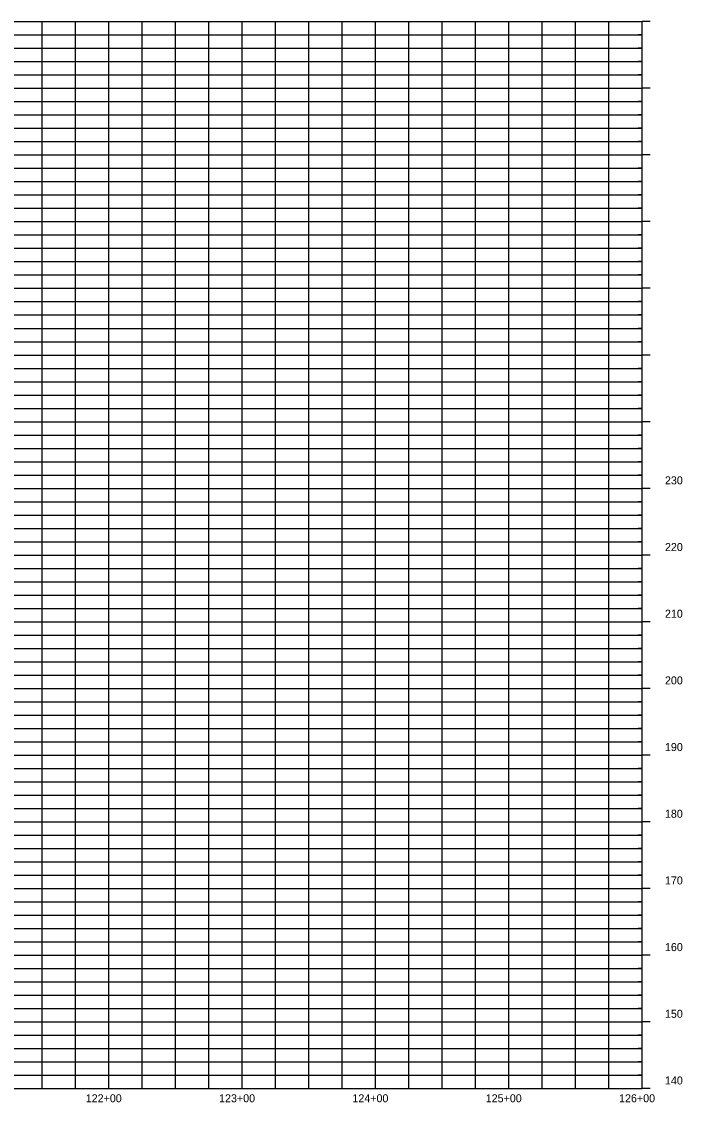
# Model space of a CAD drawing. Extents: x 1384498 to 1391279, y 1965973 to 1976560.
# Drawn here: x 1390583 to 1391079, y 1975299 to 1976110 of the extents above; entities that cross this region are included whole.
import ezdxf

# ---------------------------------------------------------------- set-up
doc = ezdxf.new("R2010")
doc.units = 0
for name, color, linetype in [('Default', 7, 'Continuous'), ('R_Axis_Annotation', 7, 'Continuous'), ('R_Grid', 7, 'Continuous'), ('R_Grid Annot', 7, 'Continuous'), ('R_Grid_Minor', 7, 'Continuous')]:
    doc.layers.add(name, color=color, linetype=linetype)

msp = doc.modelspace()

# ---------------------------------------------------------------- linework, layer by layer
at = {"layer": 'Default'}
msp.add_line((1388248.79, 1975309.84), (1390648.79, 1975309.84), dxfattribs=at)
at = {"layer": 'R_Grid'}
for p, q in [((1388248.79, 1976109.84), (1391048.79, 1976109.84)), ((1388248.79, 1976109.84), (1391048.79, 1976109.84)), ((1390648.79, 1975309.84), (1390648.79, 1976109.84)), ((1390748.79, 1975309.84), (1390748.79, 1976109.84)), ((1390848.79, 1975309.84), (1390848.79, 1976109.84)), ((1390948.79, 1975309.84), (1390948.79, 1976109.84)), ((1391048.79, 1975309.84), (1391048.79, 1976109.84)), ((1388248.79, 1976059.84), (1391048.79, 1976059.84)), ((1388248.79, 1976009.84), (1391048.79, 1976009.84)), ((1388248.79, 1975959.84), (1391048.79, 1975959.84)), ((1388248.79, 1975909.84), (1391048.79, 1975909.84)), ((1388248.79, 1975859.84), (1391048.79, 1975859.84)), ((1388248.79, 1975809.84), (1391048.79, 1975809.84)), ((1388248.79, 1975759.84), (1391048.79, 1975759.84)), ((1388248.79, 1975709.84), (1391048.79, 1975709.84)), ((1388248.79, 1975659.84), (1391048.79, 1975659.84)), ((1388248.79, 1975609.84), (1391048.79, 1975609.84)), ((1388248.79, 1975559.84), (1391048.79, 1975559.84)), ((1388248.79, 1975509.84), (1391048.79, 1975509.84)), ((1388248.79, 1975459.84), (1391048.79, 1975459.84)), ((1388248.79, 1975409.84), (1391048.79, 1975409.84)), ((1388248.79, 1975359.84), (1391048.79, 1975359.84)), ((1388248.79, 1975309.84), (1391048.79, 1975309.84))]:
    msp.add_line(p, q, dxfattribs=at)
at = {"layer": 'R_Grid Annot'}
for p, q in [((1391054.79, 1976109.84), (1391048.79, 1976109.84)), ((1391054.79, 1976109.84), (1391048.79, 1976109.84)), ((1391048.79, 1976099.84), (1391045.79, 1976099.84)), ((1391048.79, 1976089.84), (1391045.79, 1976089.84)), ((1391048.79, 1976079.84), (1391045.79, 1976079.84)), ((1391048.79, 1976069.84), (1391045.79, 1976069.84)), ((1391054.79, 1976059.84), (1391048.79, 1976059.84)), ((1391048.79, 1976049.84), (1391045.79, 1976049.84)), ((1391048.79, 1976039.84), (1391045.79, 1976039.84)), ((1391048.79, 1976029.84), (1391045.79, 1976029.84)), ((1391048.79, 1976019.84), (1391045.79, 1976019.84)), ((1391054.79, 1976009.84), (1391048.79, 1976009.84)), ((1391048.79, 1975999.84), (1391045.79, 1975999.84)), ((1391048.79, 1975989.84), (1391045.79, 1975989.84)), ((1391048.79, 1975979.84), (1391045.79, 1975979.84)), ((1391048.79, 1975969.84), (1391045.79, 1975969.84)), ((1391054.79, 1975959.84), (1391048.79, 1975959.84)), ((1391048.79, 1975949.84), (1391045.79, 1975949.84)), ((1391048.79, 1975939.84), (1391045.79, 1975939.84)), ((1391048.79, 1975929.84), (1391045.79, 1975929.84)), ((1391048.79, 1975919.84), (1391045.79, 1975919.84)), ((1391054.79, 1975909.84), (1391048.79, 1975909.84)), ((1391048.79, 1975899.84), (1391045.79, 1975899.84)), ((1391048.79, 1975889.84), (1391045.79, 1975889.84)), ((1391048.79, 1975879.84), (1391045.79, 1975879.84)), ((1391048.79, 1975869.84), (1391045.79, 1975869.84)), ((1391054.79, 1975859.84), (1391048.79, 1975859.84)), ((1391048.79, 1975849.84), (1391045.79, 1975849.84)), ((1391048.79, 1975839.84), (1391045.79, 1975839.84)), ((1391048.79, 1975829.84), (1391045.79, 1975829.84)), ((1391048.79, 1975819.84), (1391045.79, 1975819.84)), ((1391054.79, 1975809.84), (1391048.79, 1975809.84)), ((1391048.79, 1975799.84), (1391045.79, 1975799.84)), ((1391048.79, 1975789.84), (1391045.79, 1975789.84)), ((1391048.79, 1975779.84), (1391045.79, 1975779.84)), ((1391048.79, 1975769.84), (1391045.79, 1975769.84)), ((1391054.79, 1975759.84), (1391048.79, 1975759.84)), ((1391048.79, 1975749.84), (1391045.79, 1975749.84)), ((1391048.79, 1975739.84), (1391045.79, 1975739.84)), ((1391048.79, 1975729.84), (1391045.79, 1975729.84)), ((1391048.79, 1975719.84), (1391045.79, 1975719.84)), ((1391054.79, 1975709.84), (1391048.79, 1975709.84)), ((1391048.79, 1975699.84), (1391045.79, 1975699.84)), ((1391048.79, 1975689.84), (1391045.79, 1975689.84)), ((1391048.79, 1975679.84), (1391045.79, 1975679.84)), ((1391048.79, 1975669.84), (1391045.79, 1975669.84)), ((1391054.79, 1975659.84), (1391048.79, 1975659.84)), ((1391048.79, 1975649.84), (1391045.79, 1975649.84)), ((1391048.79, 1975639.84), (1391045.79, 1975639.84)), ((1391048.79, 1975629.84), (1391045.79, 1975629.84)), ((1391048.79, 1975619.84), (1391045.79, 1975619.84)), ((1391054.79, 1975609.84), (1391048.79, 1975609.84)), ((1391048.79, 1975599.84), (1391045.79, 1975599.84)), ((1391048.79, 1975589.84), (1391045.79, 1975589.84)), ((1391048.79, 1975579.84), (1391045.79, 1975579.84)), ((1391048.79, 1975569.84), (1391045.79, 1975569.84)), ((1391054.79, 1975559.84), (1391048.79, 1975559.84)), ((1391048.79, 1975549.84), (1391045.79, 1975549.84)), ((1391048.79, 1975539.84), (1391045.79, 1975539.84)), ((1391048.79, 1975529.84), (1391045.79, 1975529.84)), ((1391048.79, 1975519.84), (1391045.79, 1975519.84)), ((1391054.79, 1975509.84), (1391048.79, 1975509.84)), ((1391048.79, 1975499.84), (1391045.79, 1975499.84)), ((1391048.79, 1975489.84), (1391045.79, 1975489.84)), ((1391048.79, 1975479.84), (1391045.79, 1975479.84)), ((1391048.79, 1975469.84), (1391045.79, 1975469.84)), ((1391054.79, 1975459.84), (1391048.79, 1975459.84)), ((1391048.79, 1975449.84), (1391045.79, 1975449.84)), ((1391048.79, 1975439.84), (1391045.79, 1975439.84)), ((1391048.79, 1975429.84), (1391045.79, 1975429.84)), ((1391048.79, 1975419.84), (1391045.79, 1975419.84)), ((1391054.79, 1975409.84), (1391048.79, 1975409.84)), ((1391048.79, 1975399.84), (1391045.79, 1975399.84)), ((1391048.79, 1975389.84), (1391045.79, 1975389.84)), ((1391048.79, 1975379.84), (1391045.79, 1975379.84)), ((1391048.79, 1975369.84), (1391045.79, 1975369.84)), ((1391054.79, 1975359.84), (1391048.79, 1975359.84)), ((1391048.79, 1975349.84), (1391045.79, 1975349.84)), ((1391048.79, 1975339.84), (1391045.79, 1975339.84)), ((1391048.79, 1975329.84), (1391045.79, 1975329.84)), ((1391048.79, 1975319.84), (1391045.79, 1975319.84)), ((1391054.79, 1975309.84), (1391048.79, 1975309.84))]:
    msp.add_line(p, q, dxfattribs=at)
at = {"layer": 'R_Grid_Minor'}
for p, q in [((1390598.79, 1975309.84), (1390598.79, 1976109.84)), ((1390623.79, 1975309.84), (1390623.79, 1976109.84)), ((1390673.79, 1975309.84), (1390673.79, 1976109.84)), ((1390698.79, 1975309.84), (1390698.79, 1976109.84)), ((1390723.79, 1975309.84), (1390723.79, 1976109.84)), ((1390773.79, 1975309.84), (1390773.79, 1976109.84)), ((1390798.79, 1975309.84), (1390798.79, 1976109.84)), ((1390823.79, 1975309.84), (1390823.79, 1976109.84)), ((1390873.79, 1975309.84), (1390873.79, 1976109.84)), ((1390898.79, 1975309.84), (1390898.79, 1976109.84)), ((1390923.79, 1975309.84), (1390923.79, 1976109.84)), ((1390973.79, 1975309.84), (1390973.79, 1976109.84)), ((1390998.79, 1975309.84), (1390998.79, 1976109.84)), ((1391023.79, 1975309.84), (1391023.79, 1976109.84)), ((1388248.79, 1976099.84), (1391048.79, 1976099.84)), ((1388248.79, 1976089.84), (1391048.79, 1976089.84)), ((1388248.79, 1976079.84), (1391048.79, 1976079.84)), ((1388248.79, 1976069.84), (1391048.79, 1976069.84)), ((1388248.79, 1976049.84), (1391048.79, 1976049.84)), ((1388248.79, 1976039.84), (1391048.79, 1976039.84)), ((1388248.79, 1976029.84), (1391048.79, 1976029.84)), ((1388248.79, 1976019.84), (1391048.79, 1976019.84)), ((1388248.79, 1975999.84), (1391048.79, 1975999.84)), ((1388248.79, 1975989.84), (1391048.79, 1975989.84)), ((1388248.79, 1975979.84), (1391048.79, 1975979.84)), ((1388248.79, 1975969.84), (1391048.79, 1975969.84)), ((1388248.79, 1975949.84), (1391048.79, 1975949.84)), ((1388248.79, 1975939.84), (1391048.79, 1975939.84)), ((1388248.79, 1975929.84), (1391048.79, 1975929.84)), ((1388248.79, 1975919.84), (1391048.79, 1975919.84)), ((1388248.79, 1975899.84), (1391048.79, 1975899.84)), ((1388248.79, 1975889.84), (1391048.79, 1975889.84)), ((1388248.79, 1975879.84), (1391048.79, 1975879.84)), ((1388248.79, 1975869.84), (1391048.79, 1975869.84)), ((1388248.79, 1975849.84), (1391048.79, 1975849.84)), ((1388248.79, 1975839.84), (1391048.79, 1975839.84)), ((1388248.79, 1975829.84), (1391048.79, 1975829.84)), ((1388248.79, 1975819.84), (1391048.79, 1975819.84)), ((1388248.79, 1975799.84), (1391048.79, 1975799.84)), ((1388248.79, 1975789.84), (1391048.79, 1975789.84)), ((1388248.79, 1975779.84), (1391048.79, 1975779.84)), ((1388248.79, 1975769.84), (1391048.79, 1975769.84)), ((1388248.79, 1975749.84), (1391048.79, 1975749.84)), ((1388248.79, 1975739.84), (1391048.79, 1975739.84)), ((1388248.79, 1975729.84), (1391048.79, 1975729.84)), ((1388248.79, 1975719.84), (1391048.79, 1975719.84)), ((1388248.79, 1975699.84), (1391048.79, 1975699.84)), ((1388248.79, 1975689.84), (1391048.79, 1975689.84)), ((1388248.79, 1975679.84), (1391048.79, 1975679.84)), ((1388248.79, 1975669.84), (1391048.79, 1975669.84)), ((1388248.79, 1975649.84), (1391048.79, 1975649.84)), ((1388248.79, 1975639.84), (1391048.79, 1975639.84)), ((1388248.79, 1975629.84), (1391048.79, 1975629.84)), ((1388248.79, 1975619.84), (1391048.79, 1975619.84)), ((1388248.79, 1975599.84), (1391048.79, 1975599.84)), ((1388248.79, 1975589.84), (1391048.79, 1975589.84)), ((1388248.79, 1975579.84), (1391048.79, 1975579.84)), ((1388248.79, 1975569.84), (1391048.79, 1975569.84)), ((1388248.79, 1975549.84), (1391048.79, 1975549.84)), ((1388248.79, 1975539.84), (1391048.79, 1975539.84)), ((1388248.79, 1975529.84), (1391048.79, 1975529.84)), ((1388248.79, 1975519.84), (1391048.79, 1975519.84)), ((1388248.79, 1975499.84), (1391048.79, 1975499.84)), ((1388248.79, 1975489.84), (1391048.79, 1975489.84)), ((1388248.79, 1975479.84), (1391048.79, 1975479.84)), ((1388248.79, 1975469.84), (1391048.79, 1975469.84)), ((1388248.79, 1975449.84), (1391048.79, 1975449.84)), ((1388248.79, 1975439.84), (1391048.79, 1975439.84)), ((1388248.79, 1975429.84), (1391048.79, 1975429.84)), ((1388248.79, 1975419.84), (1391048.79, 1975419.84)), ((1388248.79, 1975399.84), (1391048.79, 1975399.84)), ((1388248.79, 1975389.84), (1391048.79, 1975389.84)), ((1388248.79, 1975379.84), (1391048.79, 1975379.84)), ((1388248.79, 1975369.84), (1391048.79, 1975369.84)), ((1388248.79, 1975349.84), (1391048.79, 1975349.84)), ((1388248.79, 1975339.84), (1391048.79, 1975339.84)), ((1388248.79, 1975329.84), (1391048.79, 1975329.84)), ((1388248.79, 1975319.84), (1391048.79, 1975319.84))]:
    msp.add_line(p, q, dxfattribs=at)

# ---------------------------------------------------------------- texts
at = {"layer": 'R_Axis_Annotation'}
for s, p in [('230', (1391065.8, 1975762.84)), ('220', (1391065.8, 1975712.84)), ('210', (1391065.8, 1975662.84)), ('200', (1391065.8, 1975612.84)), ('190', (1391065.8, 1975562.84)), ('180', (1391065.8, 1975512.84)), ('170', (1391065.8, 1975462.84)), ('160', (1391065.8, 1975412.84)), ('150', (1391065.8, 1975362.84)), ('140', (1391065.8, 1975312.84)), ('122+00', (1390631.38, 1975299.49)), ('123+00', (1390731.38, 1975299.49)), ('124+00', (1390831.38, 1975299.49)), ('125+00', (1390931.38, 1975299.49)), ('126+00', (1391031.38, 1975299.49))]:
    msp.add_text(s, height=6, dxfattribs=at).set_placement(p)

doc.saveas('drawing.dxf')
